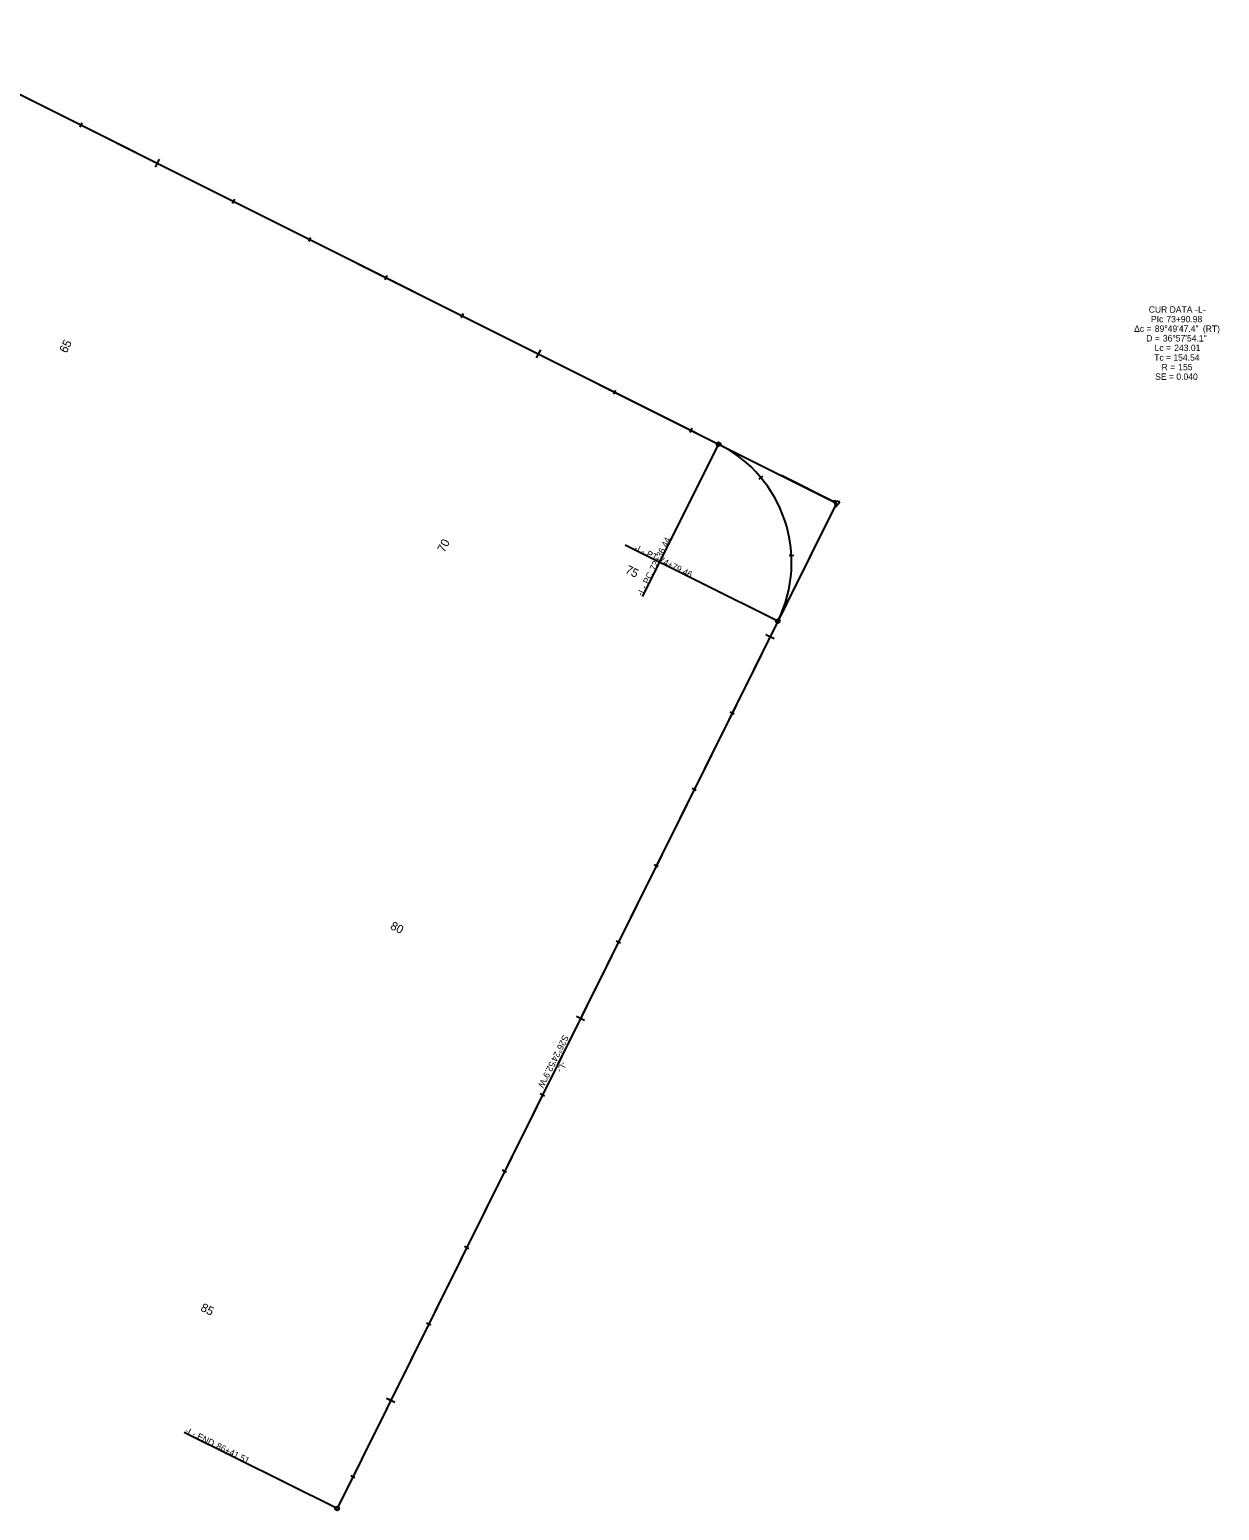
# Model space of a CAD drawing. Extents: x 2245492 to 2251120, y 200065 to 203543.
# Drawn here: x 2249724 to 2251120, y 200065 to 201802 of the extents above; entities that cross this region are included whole.
import ezdxf

# ---------------------------------------------------------------- set-up
doc = ezdxf.new("R2010")
doc.units = 0
for name, color, linetype in [('Default', 7, 'Continuous'), ('E_NCDOT_Terrain_Model_Breakline', 7, 'Continuous'), ('E_NCDOT_Terrain_Model_Contour_Minor', 7, 'Continuous'), ('E_NCDOT_Terrain_Model_Flow_Arrows', 7, 'Continuous'), ('E_NCDOT_Terrain_Model_Hole', 7, 'Continuous'), ('E_NCDOT_Terrain_Model_Points_High', 7, 'Continuous'), ('E_NCDOT_Terrain_Model_Points_Low', 7, 'Continuous'), ('E_NCDOT_Terrain_Model_Spot_Elevation', 7, 'Continuous'), ('E_NCDOT_Terrain_Model_Triangle_Vertices', 7, 'Continuous')]:
    doc.layers.add(name, color=color, linetype=linetype)

msp = doc.modelspace()

# ---------------------------------------------------------------- linework, layer by layer
at = {"layer": 'Default'}
for q in [(2250606.2, 201279.1), (2250638.6, 201182.4), (2250670.6, 201246.8)]:
    msp.add_line((2250670.6, 201246.8), q, dxfattribs=at)
msp.add_lwpolyline([(2250674.6, 201248.2), (2250667.5, 201249.6), (2250669.8, 201242.8)], close=True, dxfattribs=at)
at = {"layer": 'E_NCDOT_Terrain_Model_Contour_Minor'}
for p, q in [((2246091.1, 203538.6), (2250670.6, 201246.8)), ((2250670.6, 201246.8), (2250084.9, 200067.7))]:
    msp.add_line(p, q, dxfattribs=at)
msp.add_arc((2250463.1, 201177.4), 155, 333.5853, 63.4152, dxfattribs=at)
at = {"layer": 'E_NCDOT_Terrain_Model_Flow_Arrows'}
for p, q in [((2249876.2, 201650.3), (2249871.5, 201640.8)), ((2250323.4, 201426.6), (2250318.6, 201417.1)), ((2250597.5, 201087.7), (2250588, 201092.4)), ((2250375.1, 200639.9), (2250365.6, 200644.6)), ((2250152.7, 200192.1), (2250143.1, 200196.8))]:
    msp.add_line(p, q, dxfattribs=at)
at = {"layer": 'E_NCDOT_Terrain_Model_Hole'}
for p, q in [((2250532.4, 201316), (2250442.9, 201137.2)), ((2250601.9, 201108.4), (2250422.8, 201197.4)), ((2250084.9, 200067.7), (2249905.8, 200156.7))]:
    msp.add_line(p, q, dxfattribs=at)
for centre in [(2250532.4, 201316), (2250601.9, 201108.4), (2250084.9, 200067.7)]:
    msp.add_circle(centre, 2.25, dxfattribs=at)
at = {"layer": 'E_NCDOT_Terrain_Model_Spot_Elevation'}
for p, q in [((2249785.6, 201692.8), (2249783.2, 201687.9)), ((2249875.1, 201648), (2249872.6, 201643.1)), ((2249964.5, 201603.3), (2249962, 201598.3)), ((2250053.9, 201558.5), (2250051.5, 201553.6)), ((2250143.4, 201513.8), (2250140.9, 201508.8)), ((2250232.8, 201469), (2250230.3, 201464.1)), ((2250411.6, 201379.5), (2250409.2, 201374.6)), ((2250501.1, 201334.8), (2250498.6, 201329.8)), ((2250584, 201278.6), (2250579.8, 201275.1)), ((2250620.6, 201185.5), (2250615.1, 201185.2)), ((2250595.2, 201088.8), (2250590.3, 201091.3)), ((2250550.7, 200999.2), (2250545.8, 201001.7)), ((2250506.2, 200909.7), (2250501.3, 200912.1)), ((2250461.7, 200820.1), (2250456.8, 200822.6)), ((2250417.3, 200730.6), (2250412.3, 200733)), ((2250328.3, 200551.4), (2250323.3, 200553.9)), ((2250283.8, 200461.9), (2250278.9, 200464.3)), ((2250239.3, 200372.3), (2250234.4, 200374.8)), ((2250194.8, 200282.8), (2250189.9, 200285.2)), ((2250150.3, 200193.2), (2250145.4, 200195.7)), ((2250105.9, 200103.6), (2250100.9, 200106.1))]:
    msp.add_line(p, q, dxfattribs=at)
at = {"layer": 'E_NCDOT_Terrain_Model_Triangle_Vertices'}
for p, q in [((2246230.2, 203468.9), (2250532.4, 201316)), ((2250601.9, 201108.4), (2250084.9, 200067.7))]:
    msp.add_line(p, q, dxfattribs=at)
msp.add_arc((2250463.1, 201177.4), 155, 333.5853, 63.4152, dxfattribs=at)

# ---------------------------------------------------------------- texts
at = {"layer": 'E_NCDOT_Terrain_Model_Breakline'}
for s, p in [('CUR DATA -', (2251036.9, 201470.2)), ('PIc ', (2251039.5, 201458.9)), ('73+90.98', (2251057.6, 201458.9)), ('L', (2251094.7, 201470.2)), ('-', (2251100.6, 201470.2)), ('Δc = ', (2251019.8, 201447.7)), ('89°49\'47.4"', (2251044, 201447.7)), (' (RT)', (2251097.6, 201447.7)), ('D = ', (2251034, 201436.4)), ('Lc = ', (2251043.8, 201425.2)), ('36°57\'54.1"', (2251053.5, 201436.4)), ('243.01', (2251066.8, 201425.2)), ('Tc = ', (2251043.3, 201413.9)), ('154.54', (2251065.8, 201413.9)), ('SE = 0.040', (2251044.5, 201391.4)), ('R = ', (2251052, 201402.7)), ('155', (2251071.5, 201402.7))]:
    msp.add_text(s, height=7.5, dxfattribs=at).set_placement(p)
at = {"layer": 'E_NCDOT_Terrain_Model_Hole'}
for s, rotation, p in [('72+36.44', 63.4152, (2250457.8, 201166.8)), ('-', 333.5853, (2250432.9, 201192)), ('L', 333.5853, (2250436, 201190.4)), ('- ', 333.5853, (2250441.3, 201187.8)), ('PT', 333.5853, (2250447, 201185)), ('74+79.46', 333.5853, (2250461.6, 201177.7)), ('PC', 63.4152, (2250450, 201151.2)), ('L', 63.4152, (2250444.5, 201140.3)), ('-', 63.4152, (2250442.9, 201137.2)), ('- ', 63.4152, (2250447.1, 201145.5)), ('L', 333.5853, (2249908.9, 200155.1)), ('-', 333.5853, (2249905.8, 200156.7)), ('- ', 333.5853, (2249914.2, 200152.5)), ('END', 333.5853, (2249919.9, 200149.7)), ('86+41.51', 333.5853, (2249942.3, 200138.5))]:
    msp.add_text(s, height=7.5, rotation=rotation, dxfattribs=at).set_placement(p)
at = {"layer": 'E_NCDOT_Terrain_Model_Points_High'}
for s, p in [('S26°24\'52.9"W', (2250350.3, 200623.9)), ('L', (2250346.6, 200589.5)), ('-', (2250344, 200584.3)), ('-', (2250348.2, 200592.6))]:
    msp.add_text(s, height=7.5, rotation=243.5853, dxfattribs=at).set_placement(p)
at = {"layer": 'E_NCDOT_Terrain_Model_Points_Low'}
for s, rotation, p in [('65', 63.4152, (2249767.6, 201422)), ('70', 63.4152, (2250210.9, 201188.2)), ('75', 333.5853, (2250422.1, 201165.6)), ('80', 333.5853, (2250146.5, 200747.8)), ('85', 333.5853, (2249924, 200300.1))]:
    msp.add_text(s, height=10, rotation=rotation, dxfattribs=at).set_placement(p)

doc.saveas('drawing.dxf')
